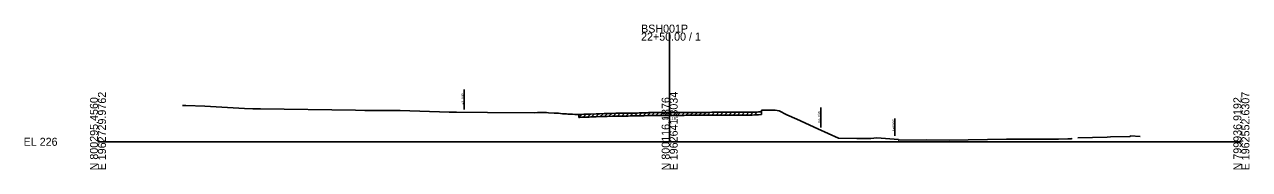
# Model space of a CAD drawing. Extents: x -26 to 1403, y -10 to 19587.
# Drawn here: x -25.7 to 402.8, y 6490.3 to 6541 of the extents above; entities that cross this region are included whole.
import ezdxf

# ---------------------------------------------------------------- set-up
doc = ezdxf.new("R2010")
doc.units = 0
for name, color, linetype in [('Default', 7, 'Continuous'), ('RD_GPK_XS_Cell', 7, 'Continuous'), ('RD_XS_ExGround', 7, 'Continuous'), ('RD_XS_ExPaveRet', 7, 'Continuous'), ('RD_XS_ExRW', 7, 'Continuous'), ('RD_XS_NewRW', 7, 'Continuous'), ('RD_XS_TX_Elev_EX', 7, 'Continuous')]:
    doc.layers.add(name, color=color, linetype=linetype)

msp = doc.modelspace()

# ---------------------------------------------------------------- linework, layer by layer
at = {"layer": 'RD_GPK_XS_Cell'}
for p, q in [((200, 6500), (200, 6538.16)), ((0, 6500), (200, 6500)), ((200, 6500), (400, 6500))]:
    msp.add_line(p, q, dxfattribs=at)
at = {"layer": 'RD_XS_ExGround'}
for points in [[(29.53, 6512.72), (30.69, 6512.66), (37.4, 6512.48), (47.26, 6511.84), (51.24, 6511.64), (54.19, 6511.53), (56.9, 6511.48), (90.1, 6511.06), (93.4, 6510.99), (104.6, 6510.95), (105.77, 6510.91), (122.91, 6510.36), (123.62, 6510.36), (124.51, 6510.34), (125.47, 6510.31), (136.24, 6510.21), (152.55, 6510.14), (153.74, 6510.19), (154.35, 6510.23), (154.89, 6510.22), (155.5, 6510.21), (156.92, 6510.18), (157.58, 6510.15), (159.6, 6510.05), (160.35, 6510.02), (161.11, 6509.95), (162.49, 6509.82), (162.85, 6509.78), (163.22, 6509.79), (163.9, 6509.72), (164.39, 6509.69), (165.96, 6509.62), (166.82, 6509.59), (168.44, 6509.51), (169.17, 6509.58), (169.97, 6509.61), (171.83, 6509.66), (172.44, 6509.68), (174.34, 6509.74), (175.57, 6509.78), (177.11, 6509.84), (178.09, 6509.87), (179.88, 6509.94), (181.19, 6509.98), (182.67, 6509.99), (183.7, 6510), (185.43, 6510.01), (186.73, 6510.02), (188.25, 6510.04), (188.61, 6510.05), (189.32, 6510.07), (191.03, 6510.12), (192.4, 6510.17), (192.73, 6510.19), (193.05, 6510.2), (196.66, 6510.18), (197.61, 6510.18), (198.85, 6510.18), (199.31, 6510.18), (200, 6510.18), (200.55, 6510.19), (201.69, 6510.19), (202.22, 6510.2), (203.55, 6510.21), (205.02, 6510.24), (205.98, 6510.25), (207.42, 6510.26), (207.81, 6510.27), (209.27, 6510.27), (210.98, 6510.28), (212.06, 6510.29), (213.39, 6510.29), (214.79, 6510.3), (216.16, 6510.31), (217.55, 6510.33), (219.2, 6510.34), (219.58, 6510.33), (221.73, 6510.3), (223.17, 6510.31), (224.48, 6510.32), (225.92, 6510.32), (227.29, 6510.33), (227.81, 6510.34), (228.82, 6510.36), (229.98, 6510.39), (231.09, 6510.42), (232.07, 6510.49), (232.17, 6511.04), (233.2, 6511.04), (236.92, 6511.04), (238.35, 6510.77), (241.04, 6509.37), (244.45, 6507.87), (251.82, 6504.5), (259.05, 6501.22), (265.43, 6501.15), (270.36, 6501.12), (272.43, 6501.32), (280.03, 6500.78), (280.13, 6500.53), (289.89, 6500.65), (297.73, 6500.61), (317.83, 6500.93), (318.96, 6500.92), (322.63, 6500.92), (322.99, 6500.92), (323.73, 6500.91), (324.83, 6500.92), (326.14, 6500.93), (326.94, 6500.94), (336.02, 6500.95), (339.3, 6501.01), (340.61, 6501.04), (340.71, 6501.29)], [(342.81, 6501.37), (353.1, 6501.65), (354.17, 6501.7), (361.05, 6501.82), (361.16, 6502.07), (364.56, 6501.85)]]:
    msp.add_lwpolyline(points, dxfattribs=at)
at = {"layer": 'RD_XS_ExPaveRet'}
for p, q in [((168.21, 6508.52), (169.28, 6509.58)), ((168.21, 6508.52), (168.21, 6509.52)), ((169.71, 6508.6), (170.75, 6509.63)), ((171.21, 6508.64), (172.25, 6509.67)), ((172.71, 6508.69), (173.75, 6509.72)), ((174.21, 6508.73), (175.25, 6509.77)), ((175.71, 6508.79), (176.75, 6509.82)), ((177.21, 6508.84), (178.25, 6509.88)), ((178.71, 6508.9), (179.75, 6509.94)), ((180.21, 6508.95), (181.24, 6509.98)), ((181.71, 6508.99), (182.72, 6509.99)), ((183.21, 6508.99), (184.22, 6510)), ((184.71, 6509), (185.72, 6510.01)), ((186.21, 6509.02), (187.23, 6510.03)), ((187.71, 6509.03), (188.73, 6510.05)), ((189.21, 6509.07), (190.24, 6510.09)), ((190.71, 6509.11), (191.75, 6510.14)), ((192.21, 6509.16), (193.25, 6510.2)), ((193.71, 6509.2), (194.71, 6510.19)), ((195.21, 6509.19), (196.21, 6510.19)), ((196.71, 6509.18), (197.71, 6510.18)), ((198.21, 6509.18), (199.21, 6510.18)), ((199.71, 6509.18), (200.72, 6510.19)), ((201.21, 6509.19), (202.22, 6510.2)), ((202.71, 6509.2), (203.72, 6510.21)), ((204.21, 6509.22), (205.23, 6510.24)), ((205.71, 6509.25), (206.73, 6510.26)), ((207.21, 6509.26), (208.22, 6510.27)), ((208.71, 6509.27), (209.72, 6510.27)), ((210.21, 6509.27), (211.22, 6510.28)), ((211.71, 6509.28), (212.72, 6510.29)), ((213.21, 6509.29), (214.22, 6510.3)), ((214.71, 6509.3), (215.72, 6510.31)), ((216.21, 6509.31), (217.23, 6510.32)), ((217.71, 6509.33), (218.72, 6510.34)), ((219.21, 6509.34), (220.2, 6510.32)), ((220.71, 6509.32), (221.7, 6510.3)), ((222.21, 6509.31), (223.22, 6510.31)), ((223.71, 6509.32), (224.72, 6510.32)), ((225.21, 6509.32), (226.22, 6510.32)), ((226.71, 6509.33), (227.73, 6510.34)), ((228.21, 6509.35), (229.23, 6510.37)), ((229.71, 6509.38), (230.74, 6510.41)), ((229.98, 6509.39), (231.09, 6509.42)), ((231.09, 6509.42), (232.07, 6509.49)), ((232.07, 6510.49), (232.07, 6509.49)), ((168.21, 6508.52), (168.44, 6508.51)), ((168.44, 6508.51), (169.17, 6508.58)), ((169.17, 6508.58), (169.97, 6508.61)), ((169.97, 6508.61), (171.83, 6508.66)), ((171.83, 6508.66), (172.44, 6508.68)), ((172.44, 6508.68), (174.34, 6508.74)), ((174.34, 6508.74), (175.57, 6508.78)), ((175.57, 6508.78), (177.11, 6508.84)), ((177.11, 6508.84), (178.09, 6508.87)), ((178.09, 6508.87), (179.88, 6508.94)), ((179.88, 6508.94), (181.19, 6508.98)), ((181.19, 6508.98), (182.67, 6508.99)), ((182.67, 6508.99), (183.7, 6509)), ((183.7, 6509), (185.43, 6509.01)), ((185.43, 6509.01), (186.73, 6509.02)), ((186.73, 6509.02), (188.25, 6509.04)), ((188.25, 6509.04), (188.61, 6509.05)), ((188.61, 6509.05), (189.32, 6509.07)), ((189.32, 6509.07), (191.03, 6509.12)), ((191.03, 6509.12), (192.4, 6509.17)), ((192.4, 6509.17), (192.73, 6509.19)), ((192.73, 6509.19), (193.05, 6509.2)), ((193.05, 6509.2), (196.66, 6509.18)), ((196.66, 6509.18), (197.61, 6509.18)), ((197.61, 6509.18), (198.85, 6509.18)), ((198.85, 6509.18), (199.31, 6509.18)), ((199.31, 6509.18), (200, 6509.18)), ((200, 6509.18), (200.55, 6509.19)), ((200.55, 6509.19), (201.69, 6509.19)), ((201.69, 6509.19), (202.22, 6509.2)), ((202.22, 6509.2), (203.55, 6509.21)), ((203.55, 6509.21), (205.02, 6509.24)), ((205.02, 6509.24), (205.98, 6509.25)), ((205.98, 6509.25), (207.42, 6509.26)), ((207.42, 6509.26), (207.81, 6509.27)), ((207.81, 6509.27), (209.27, 6509.27)), ((209.27, 6509.27), (210.98, 6509.28)), ((210.98, 6509.28), (212.06, 6509.29)), ((212.06, 6509.29), (213.39, 6509.29)), ((213.39, 6509.29), (214.79, 6509.3)), ((214.79, 6509.3), (216.16, 6509.31)), ((216.16, 6509.31), (217.55, 6509.33)), ((217.55, 6509.33), (219.2, 6509.34)), ((219.2, 6509.34), (219.58, 6509.33)), ((219.58, 6509.33), (221.73, 6509.3)), ((221.73, 6509.3), (223.17, 6509.31)), ((223.17, 6509.31), (224.48, 6509.32)), ((224.48, 6509.32), (225.92, 6509.32)), ((225.92, 6509.32), (227.29, 6509.33)), ((227.29, 6509.33), (227.81, 6509.34)), ((227.81, 6509.34), (228.82, 6509.36)), ((228.82, 6509.36), (229.98, 6509.39))]:
    msp.add_line(p, q, dxfattribs=at)
at = {"layer": 'RD_XS_ExRW'}
for p, q in [((128.07, 6511.29), (128.07, 6518.29)), ((252.84, 6505.03), (252.84, 6512.03))]:
    msp.add_line(p, q, dxfattribs=at)
at = {"layer": 'RD_XS_NewRW'}
msp.add_line((278.76, 6508.13), (278.76, 6502.13), dxfattribs=at)

# ---------------------------------------------------------------- texts
at = {"layer": 'Default'}
msp.add_text('-', height=0.0001, dxfattribs=at).set_placement((0, 6500))
at = {"layer": 'RD_GPK_XS_Cell'}
for s, p in [('BSH001P', (190, 6538.16)), ('22+50.00 / 1', (190, 6535.36)), ('EL 226', (-26, 6498.6))]:
    msp.add_text(s, height=2.8, dxfattribs=at).set_placement(p)
for s, p in [('N 800295.4560', (0, 6490)), ('E 1962729.9762', (2.8, 6490)), ('N 800116.1876', (200, 6490)), ('E 1962641.3034', (202.8, 6490)), ('N 799936.9192', (400, 6490)), ('E 1962552.6307', (402.8, 6490))]:
    msp.add_text(s, height=2.8, rotation=90, dxfattribs=at).set_placement(p)
at = {"layer": 'RD_XS_ExRW'}
for p in [(127.82, 6512.96), (252.59, 6506.71)]:
    msp.add_text('EX. R/W ', height=0.75, rotation=90, dxfattribs=at).set_placement(p)
at = {"layer": 'RD_XS_NewRW'}
msp.add_text('NEW R/W ', height=0.65, rotation=90, dxfattribs=at).set_placement((278.49, 6503.69))
at = {"layer": 'RD_XS_TX_Elev_EX'}
msp.add_text('236.18', height=1, dxfattribs=at).set_placement((197.95, 6507.68))

doc.saveas('drawing.dxf')
